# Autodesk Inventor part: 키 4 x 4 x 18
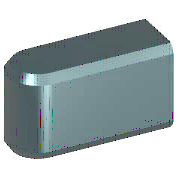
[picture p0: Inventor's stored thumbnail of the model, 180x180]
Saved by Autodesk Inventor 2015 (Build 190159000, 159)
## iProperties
IsCustomPart: 1
Created: 2012-02
Part Number: 키 4 x 4 x 18
Material: 강철, 연강
Description: 키 및 해당 키홈
Document SubType Name: Modeling
Standard: KS B 1311
Designer: mduedu
Standards Organization: KS
Language: ko-KR
Size Designation: 4 x 4 x 18
Categories: <MemberInstance><Categories><Category DisplayName="샤프트 부품" InternalName="7f7aeb1f-a693-4053-b835-cee3144e0d98" Mnemonic="SHFT"><Category DisplayName="키" Interna
Density: 1 g/cm^3
Appearance: 주황색
Author: mduedu
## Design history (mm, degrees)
sketch "스케치1"
  geometry: L1 (2, 2)-(18, 2); L2 (18, 2)-(18, -2); L3 (18, -2)-(2, -2); L4 (0, 7)-(0, -7) reference; L5 (-5, 0)-(30, 0) reference; A1 r 2 centre (2, 0) between (2, 2) and (2, -2)
  constraints: 6 end point, 3 tangent, 2 point on circle, 1 centre point, 1 horizontal, 1 parallel, 1 perpendicular, 1 point on line
  dimensions: "d0" = 2 radius of A1 (= 0.5 x PB); "d7" = 18 distance between parallel lines of L2 L4 (= NLG)
workplane "Work Plane1"
workplane "Work Plane2"
extrude "본체1" new body sketch "스케치1" taper "d3" = 0 deg; stored distance "d4" = 10
workaxis "Work Axis1"
workplane "Work Plane4"
body "Solid1"
chamfer "모따기1" distance "d8" = 0.25 (= PHH); stored, may be unused: second distance "d9" = 0.25 (= PHH), angle "d13" = 45 deg
other parameters: "d1" = -2.5 (= -PNT), "d2" = 1.5 (= PH - PNT), "NLG" = 18 [user parameter; used in 2 equation terms], "PB" = 4 [user parameter; used in 1 equation term], "PNT" = 2.5 [user parameter; used in 2 equation terms], "PH" = 4 [user parameter; used in 1 equation term], "PHH" = 0.25 [user parameter; used in 2 equation terms], "d10" = 0, "d16" = 0, "d17" = 0, "d18" = 0, "RR" = 0.08 [user parameter], "WDMAX" = 12 [user parameter], "PLB1" = 18 (= NLG) [user parameter], "PUEB" = 1.8 [user parameter]
